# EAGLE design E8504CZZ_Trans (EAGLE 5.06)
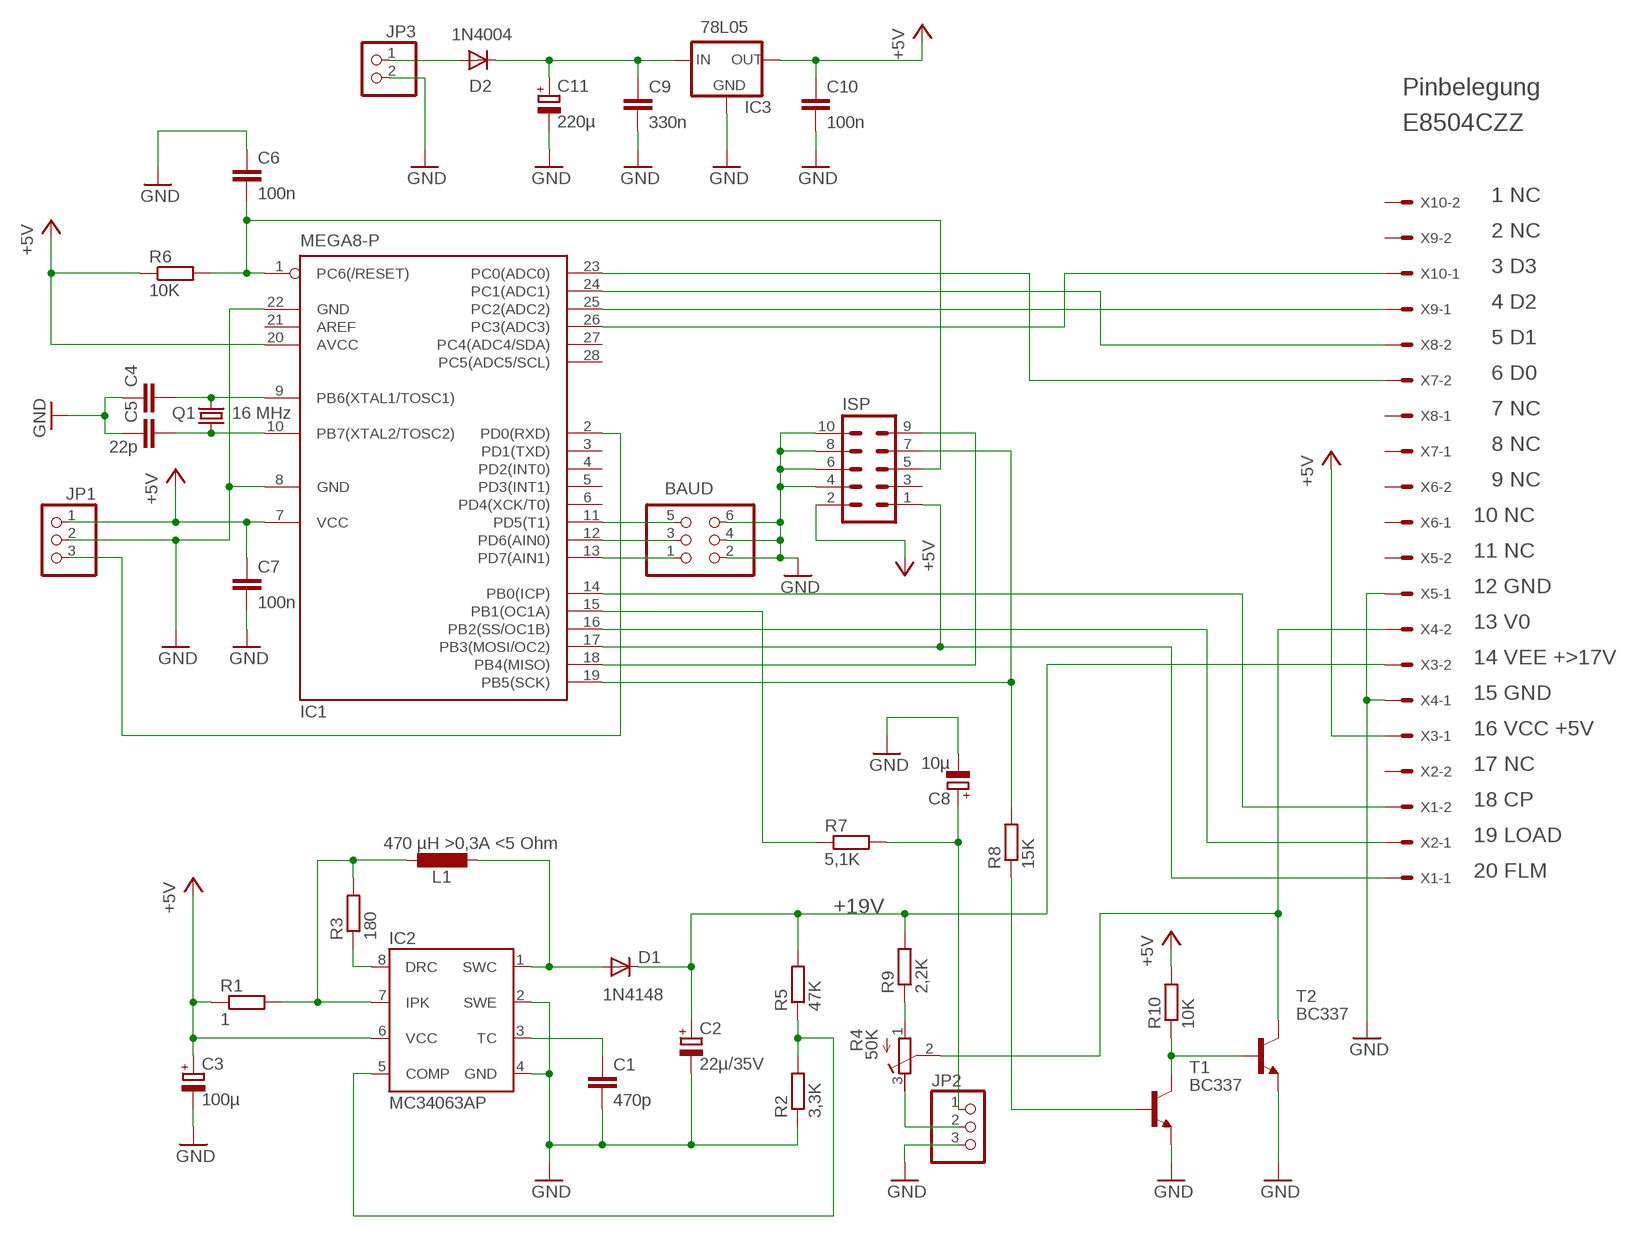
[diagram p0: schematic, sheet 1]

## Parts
BAUD  PINHD-2X3  [2X03]
C1  470p  C-EU025-024X044  [C025-024X044]
C2  22µ/35V  CPOL-EUE2-5  [E2-5]
C3  100µ  CPOL-EUE2.5-6  [E2,5-6]
C4  C-EU025-024X044  [C025-024X044]
C5  22p  C-EU025-024X044  [C025-024X044]
C6  100n  C-EU025-024X044  [C025-024X044]
C7  100n  C-EU025-024X044  [C025-024X044]
C8  10µ  CPOL-EUE2-5  [E2-5]
C9  330n  C-EU025-024X044  [C025-024X044]
C10  100n  C-EU025-024X044  [C025-024X044]
C11  220µ  CPOL-EUE3.5-8  [E3,5-8]
D1  1N4148  1N4148DO35-7  [DO35-7]
D2  1N4004  [DO41-10]
IC1  MEGA8-P  [DIL28-3]
IC2  MC34063AP  [DIL-08]
IC3  78L05  78LXX  [78LXX]
ISP  ML10  [ML10]
JP1  PINHD-1X3  [1X03]
JP2  PINHD-1X3  [1X03]
JP3  PINHD-1X2  [1X02]
L1  470 µH >0,3A <5 Ohm  L-EU0204/5  [0204/5]
Q1  16 MHz  CRYSTALHC49S  [HC49/S]
R1  1  R-EU_0207/10  [0207/10]
R2  3,3K  R-EU_0207/10  [0207/10]
R3  180  R-EU_0207/10  [0207/10]
R4  50K  R-TRIMM64W  [RTRIM64W]
R5  47K  R-EU_0207/10  [0207/10]
R6  10K  R-EU_0207/10  [0207/10]
R7  5,1K  R-EU_0207/10  [0207/10]
R8  15K  R-EU_0207/15  [0207/15]
R9  2,2K  R-EU_0207/10  [0207/10]
R10  10K  R-EU_0207/10  [0207/10]
T1  BC337  [TO92]
T2  BC337  [TO92]
X1  87758-0216  [87758-0216]
X2  87758-0216  [87758-0216]
X3  87758-0216  [87758-0216]
X4  87758-0216  [87758-0216]
X5  87758-0216  [87758-0216]
X6  87758-0216  [87758-0216]
X7  87758-0216  [87758-0216]
X8  87758-0216  [87758-0216]
X9  87758-0216  [87758-0216]
X10  87758-0216  [87758-0216]

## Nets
+5V: C3.+ C7.1 C10.1 IC1.7(VCC) IC1.20(AVCC) IC2.6(VCC) IC3.OUT ISP.2 JP1.1 R1.1 R6.1 R10.2 X3.1
+19V: C2.+ D1.C R5.2 R9.2 X3.2
CP: IC1.14(PB0(ICP)) X1.2
D0: IC1.23(PC0(ADC0)) X7.2
D1: IC1.24(PC1(ADC1)) X8.2
D2: IC1.25(PC2(ADC2)) X9.1
D3: IC1.26(PC3(ADC3)) X10.1
FLM: IC1.17(PB3(MOSI/OC2)) ISP.1 X1.1
GND: BAUD.2 BAUD.4 BAUD.6 C1.2 C2.- C3.- C4.1 C5.1 C6.1 C7.2 C8.- C9.2 C10.2 C11.- IC1.8(GND) IC1.22(GND) IC2.2(SWE) IC2.4(GND) IC3.GND ISP.4 ISP.6 ISP.8 ISP.10 JP1.2 JP2.3 JP3.2 R2.1 T1.1(E) T2.1(E) X4.1 X5.1
LOAD: IC1.16(PB2(SS/OC1B)) X2.1
MISO: IC1.18(PB4(MISO)) ISP.9
N$1: IC1.2(PD0(RXD)) JP1.3
N$2: JP2.2 R4.3(A)
N$6: IC1.15(PB1(OC1A)) R7.1
N$8: C8.+ JP2.1 R7.2
N$9: D2.A JP3.1
N$10: IC2.5(COMP) R2.2 R5.1
N$11: C5.2 IC1.10(PB7(XTAL2/TOSC2)) Q1.1
N$12: C4.2 IC1.9(PB6(XTAL1/TOSC1)) Q1.2
N$13: IC2.7(IPK) L1.1 R1.2 R3.2
N$14: BAUD.1 IC1.13(PD7(AIN1))
N$15: IC2.8(DRC) R3.1
N$16: C9.1 C11.+ D2.C IC3.IN
N$17: D1.A IC2.1(SWC) L1.2
N$19: BAUD.3 IC1.12(PD6(AIN0))
N$20: BAUD.5 IC1.11(PD5(T1))
N$21: C1.1 IC2.3(TC)
N$23: R10.1 T1.3(C) T2.2(B)
N$24: R8.1 T1.2(B)
N$25: R4.1(E) R9.1
RESET: C6.2 IC1.1(PC6(/RESET)) ISP.5 R6.2
SCK: IC1.19(PB5(SCK)) ISP.7 R8.2
VSS: R4.2(S) T2.3(C) X4.2
Unconnected: IC1.3(PD1(TXD)) IC1.4(PD2(INT0)) IC1.5(PD3(INT1)) IC1.6(PD4(XCK/T0)) IC1.21(AREF) IC1.27(PC4(ADC4/SDA)) IC1.28(PC5(ADC5/SCL)) ISP.3 X2.2 X5.2 X6.1 X6.2 X7.1 X8.1 X9.2 X10.2

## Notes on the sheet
- Pinbelegung
- E8504CZZ
- 1 NC
- 2 NC
- 3 D3
- 4 D2
- 5 D1
- 6 D0
- 7 NC
- 8 NC
- 9 NC
- 10 NC
- 11 NC
- 12 GND
- 13 V0
- 14 VEE +>17V
- 15 GND
- 16 VCC +5V
- 17 NC
- 18 CP
- 19 LOAD
- 20 FLM

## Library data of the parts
BAUD = pinhead:PINHD-2X3: PIN HEADER
C1 C4-C7 C9 C10 = rcl:C-EU: CAPACITOR, European symbol
C2 C3 C8 C11 = rcl:CPOL-EU: POLARIZED CAPACITOR, European symbol
D1 = diode:1N4148: DIODE
D2 = diode:1N4004: DIODE
IC1 = atmel:MEGA8-P: MICROCONTROLLER 8 Kbytes FLASH, 1 kbytes SRAM, 512 bytes EEPROM, USART, 4-channel 10 bit ADC, 2-channel 8 bit ADC Pin compatible with Atmega48, ATMega88, ATMega168 Source: avr.lbr
IC2 = v-reg-3:MC34063A: 1.5A Step-Up/Down/Inverting Switching Regulator NPN Darlington Switch, Vin 3V to 40V, Current Limiter Input, adjustable Frequency up to 100kHz
IC3 = v-reg:78LXX: VOLTAGE REGULATOR
ISP = con-harting-ml:ML10: HARTING
JP1 JP2 = pinhead:PINHD-1X3: PIN HEADER
JP3 = pinhead:PINHD-1X2: PIN HEADER
L1 = rcl:L-EU: INDUCTOR, European symbol
Q1 = crystal:CRYSTAL: CRYSTAL
R1-R3 R5-R10 = rcl:R-EU_: RESISTOR, European symbol
R4 = rcl:R-TRIMM: Trimm resistor
T1 = transistor-npn:BC337*: NPN Transistor
T2 = transistor:BC337: NPN TRANSISTOR
X1-X10 = con-molex:87758-0216: 2 Pin - 2mm Dual Row Single Wafer, Vertical T/H HDR

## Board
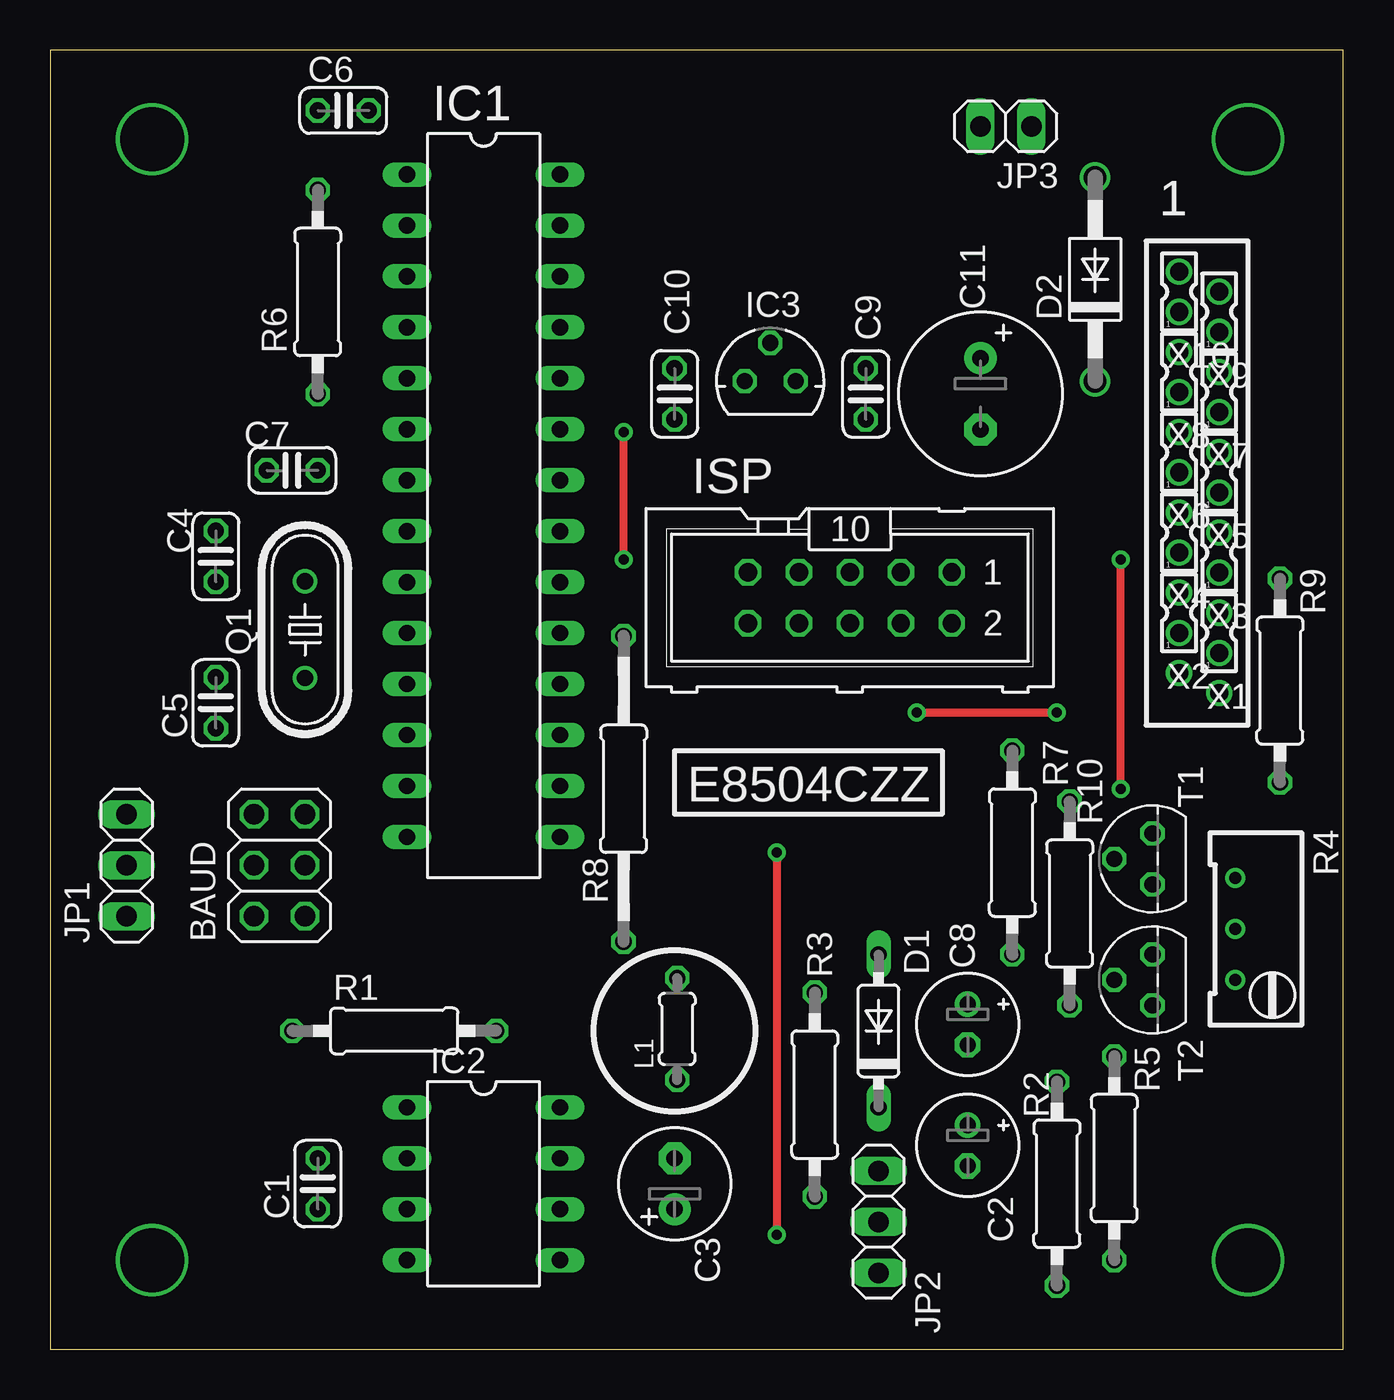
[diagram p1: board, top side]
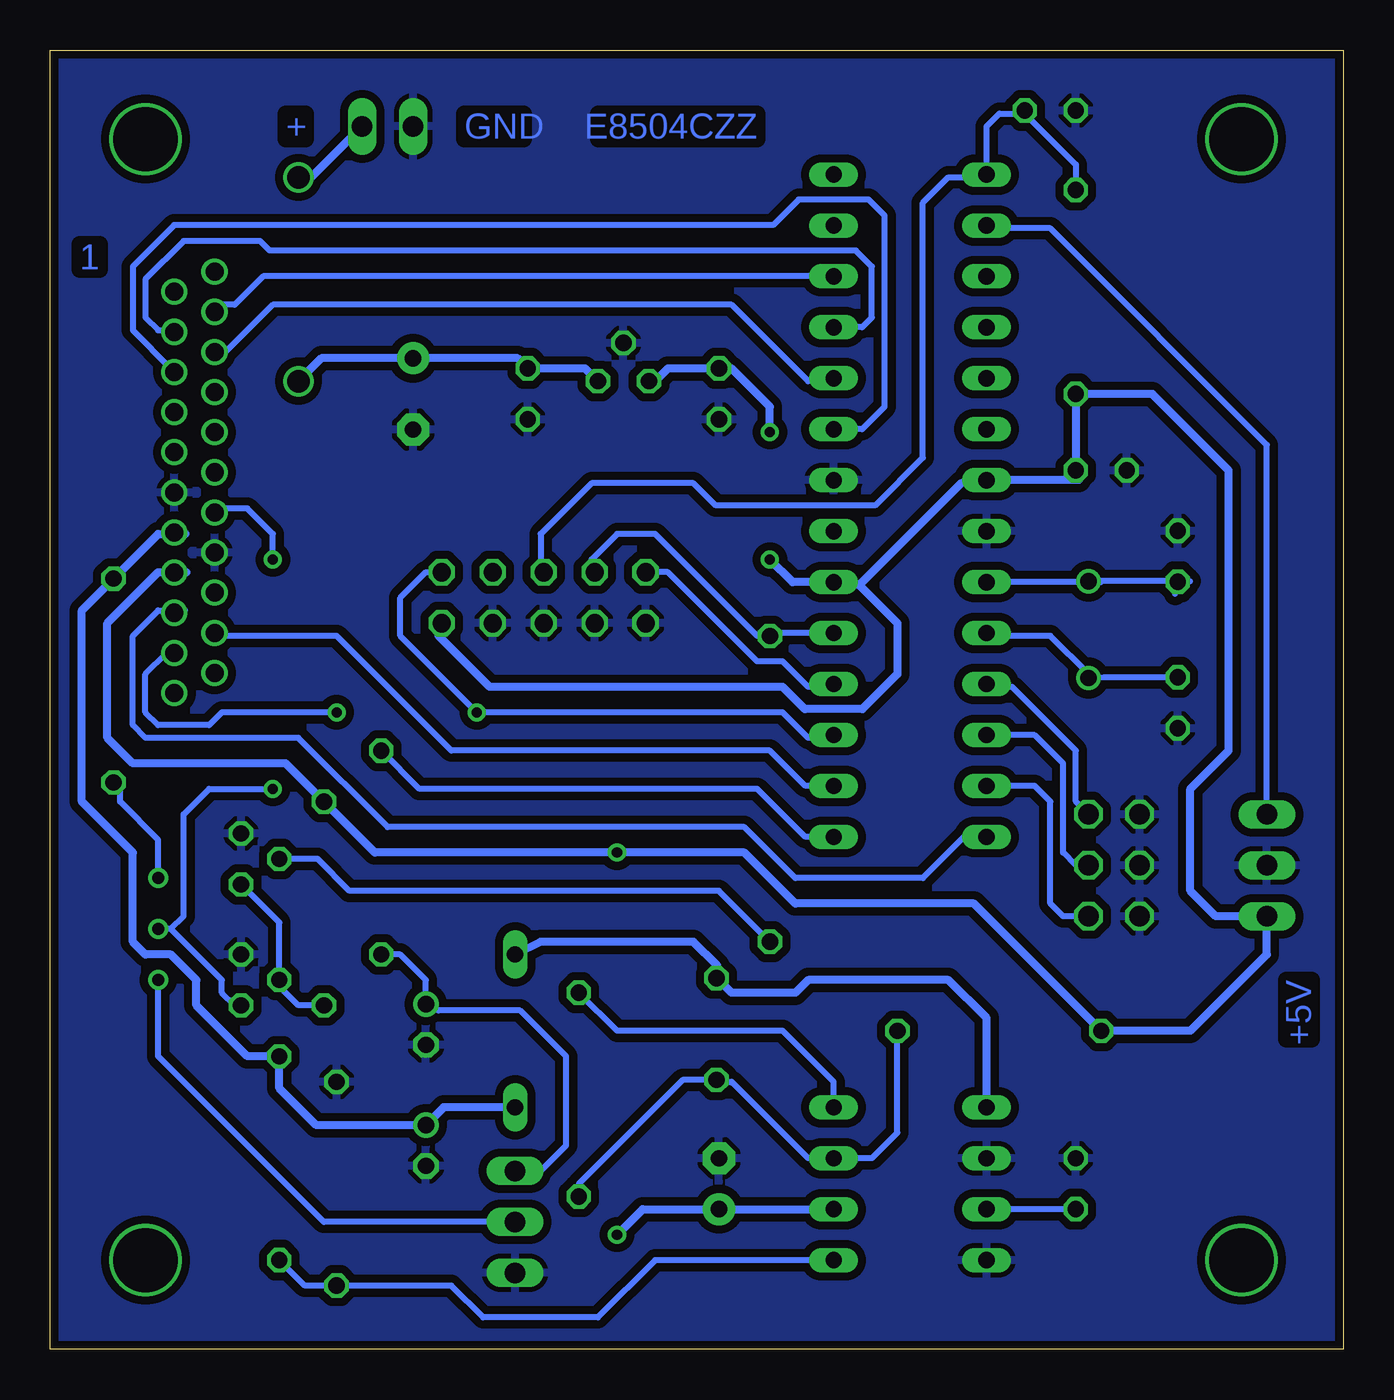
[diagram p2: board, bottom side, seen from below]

Size 64.44 x 64.76 mm. Coordinates in mm from the lower left corner, seen from the top.
Outline: 0,0 64.44,0 64.44,64.76 0,64.76 0,0
Copper layers (1*16): Top 0.035mm / dielectric 1.5mm / Bottom 0.035mm
Design rules "ZWILLING": minimum track width 0.2mm, minimum drill 0.5mm, track to track 0.2mm, track to pad 0.2mm, pad to pad 0.15mm, via to via 0.2mm, smd to smd 0mil, copper to edge 0.2mm, drill to drill 0.2mm, minimum pad ring 0.2mm, minimum via ring 0.2mm, stop-mask expansion 0.1mm, vias tented up to drill 0mil, thermal gap 10mil

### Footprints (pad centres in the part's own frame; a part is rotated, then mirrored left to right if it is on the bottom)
2X03 = drill 1.016 octagon: 1 -2.54,-1.27; 2 -2.54,1.27; 3 0,-1.27; 4 0,1.27; 5 2.54,-1.27; 6 2.54,1.27
C025-024X044 = drill 0.813 octagon: 1 -1.27,0; 2 1.27,0
E2-5 = drill 0.813 pad 1.27 round: + -1.016,0 | drill 0.813 pad 1.27 octagon: - 1.016,0
E2,5-6 = drill 0.813 pad 1.6 round: + -1.27,0 | drill 0.813 pad 1.6 octagon: - 1.27,0
E3,5-8 = drill 0.813 pad 1.6 round: + -1.778,0 | drill 0.813 pad 1.6 octagon: - 1.778,0
DO35-7 = drill 0.813 long: A 3.81,0; C -3.81,0
DO41-10 = drill 1.118 round: A 5.08,0; C -5.08,0
DIL28-3 = drill 0.813 long: 1 -16.51,-3.81; 2 -13.97,-3.81; 3 -11.43,-3.81; 4 -8.89,-3.81; 5 -6.35,-3.81; 6 -3.81,-3.81; 7 -1.27,-3.81; 8 1.27,-3.81; 9 3.81,-3.81; 10 6.35,-3.81; 11 8.89,-3.81; 12 11.43,-3.81; 13 13.97,-3.81; 14 16.51,-3.81; 15 16.51,3.81; 16 13.97,3.81; 17 11.43,3.81; 18 8.89,3.81; 19 6.35,3.81; 20 3.81,3.81; 21 1.27,3.81; 22 -1.27,3.81; 23 -3.81,3.81; 24 -6.35,3.81; 25 -8.89,3.81; 26 -11.43,3.81; 27 -13.97,3.81; 28 -16.51,3.81
DIL-08 = drill 0.813 long: 1 -3.81,-3.81; 2 -1.27,-3.81; 3 1.27,-3.81; 4 3.81,-3.81; 5 3.81,3.81; 6 1.27,3.81; 7 -1.27,3.81; 8 -3.81,3.81
78LXX = drill 0.813 octagon: GND 0,1.905; IN 1.27,0; OUT -1.27,0
ML10 = drill 0.914 octagon: 1 -5.08,-1.27; 2 -5.08,1.27; 3 -2.54,-1.27; 4 -2.54,1.27; 5 0,-1.27; 6 0,1.27; 7 2.54,-1.27; 8 2.54,1.27; 9 5.08,-1.27; 10 5.08,1.27
1X03 = drill 1.016 long: 1 -2.54,0; 2 0,0; 3 2.54,0
1X02 = drill 1.016 long: 1 -1.27,0; 2 1.27,0
0204/5 = drill 0.813 octagon: 1 -2.54,0; 2 2.54,0
HC49/S = drill 0.813 round: 1 -2.413,0; 2 2.413,0
0207/10 = drill 0.813 octagon: 1 -5.08,0; 2 5.08,0
RTRIM64W = drill 0.61 round: 1 1.27,-2.54; 2 1.27,0; 3 1.27,2.54
0207/15 = drill 0.813 octagon: 1 -7.62,0; 2 7.62,0
TO92 = drill 0.813 octagon: 1 1.27,0; 2 0,1.905; 3 -1.27,0
87758-0216 = drill 0.9 pad 1.27 round: 1 0,-1; 2 0,1

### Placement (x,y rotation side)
BAUD  11.43,24.13 90 top
C1  13.34,8.26 90 top
C2  45.72,10.16 270 top
C3  31.11,8.26 90 top
C4  8.26,39.53 270 top
C5  8.26,32.23 90 top
C6  14.61,61.75 0 top
C7  12.06,43.81 180 top
C8  45.72,16.19 270 top
C9  40.64,47.62 270 top
C10  31.11,47.62 270 top
C11  46.35,47.62 270 top
D1  41.27,15.88 90 top
D2  52.07,53.34 90 top
IC1  21.59,42.05 270 top
IC2  21.59,8.26 270 top
IC3  35.88,48.26 0 top
ISP  39.85,37.47 180 top
JP1  3.81,24.13 90 top
JP2  41.27,6.35 270 top
JP3  47.62,60.96 180 top
L1  31.24,15.97 90 top
Q1  12.7,35.88 90 top
R1  17.14,15.88 0 top
R2  50.16,8.26 270 top
R3  38.1,12.7 270 top
R4  60.33,20.95 180 top
R5  53.02,9.53 90 top
R6  13.34,52.7 90 top
R7  47.94,24.77 270 top
R8  28.57,27.94 90 top
R9  61.28,33.34 90 top
R10  50.8,22.23 90 top
T1  54.93,24.45 90 top
T2  54.93,18.41 90 top
X1  58.25,35.72 0 top
X2  56.25,36.72 0 top
X3  58.25,39.72 0 top
X4  56.25,40.72 0 top
X5  58.25,43.72 0 top
X6  56.25,44.72 0 top
X7  58.25,47.72 0 top
X8  56.25,48.72 0 top
X9  58.25,51.72 0 top
X10  56.25,52.72 0 top

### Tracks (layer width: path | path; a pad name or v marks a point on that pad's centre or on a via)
+5V  (via drill 0.5)
  Top 0.406: v36.2,24.77 v36.2,5.71 | v28.57,39.37 v28.57,45.72
  Bottom 0.406: IC2.6 C3.+ 34.92,6.99 v36.2,5.71 | X3.1 57.63,38.73 59.05,38.73 61.59,36.2 61.59,30.48 60.33,29.21 52.7,29.21 R10.2 48.26,24.77 v36.2,24.77 29.84,24.77 27.3,22.23 18.41,22.23 R1.1 7.62,15.88 3.81,19.68 JP1.1 6.35,21.59 7.62,22.86 7.62,27.94 5.71,29.84 5.71,43.81 9.53,47.62 R6.1 C7.1 13.18,43.34 17,43.34 IC1.7 17.92,43.18 19.05,43.18 24.13,38.1 | 24.13,38.1 22.23,36.2 22.23,33.66 23.97,31.91 26.83,31.91 27.94,33.02 42.55,33.02 45.09,35.56 45.09,36.04 ISP.2 | 24.13,38.1 25.26,38.1 IC1.20 27.45,38.24 v28.57,39.37 | IC3.OUT 34.29,48.26 33.66,48.9 C10.1 30.48,48.9 28.57,46.99 v28.57,45.72
+19V
  Bottom 0.406: X3.2 57.69,40.64 59.05,40.64 62.87,36.83 | D1.C 44.83,12.06 C2.+ 51.18,11.18 53.02,13.02 R5.2 54.61,14.61 57.15,17.14 57.15,18.41 58.42,19.68 59.69,19.68 60.33,20.32 60.33,24.77 62.87,27.3 62.87,36.83 | 62.87,36.83 R9.2
CP
  Bottom 0.305: IC1.14 18.91,25.54 20.95,23.5 27.3,23.5 29.84,26.04 47.62,26.04 52.07,30.48 59.69,30.48 60.33,31.11 60.33,35.56 59.05,36.83 57.73,36.83 X1.2
D0
  Bottom 0.305: IC1.23 23.99,45.86 22.86,46.99 22.86,56.52 23.65,57.31 27.15,57.31 28.42,56.04 58.26,56.04 60.33,53.98 60.33,50.8 58.42,48.9 57.8,48.9 X7.2
D1
  Bottom 0.305: IC1.24 25.54,48.26 26.67,48.26 30.48,52.07 53.34,52.07 55.88,49.53 56.06,49.53 X8.2
D2
  Bottom 0.305: IC1.25 23.99,50.94 23.5,51.44 23.5,53.98 24.29,54.77 53.5,54.77 53.98,55.24 57.78,55.24 59.69,53.34 59.69,51.44 59.05,50.8 58.34,50.8 X9.1
D3
  Bottom 0.305: IC1.26 53.83,53.48 55.24,52.07 55.9,52.07 X10.1
FLM  (via drill 0.5)
  Top 0.406: v43.18,31.75 v50.16,31.75
  Bottom 0.305: X1.1 58.63,34.72 59.69,33.66 59.69,31.75 59.05,31.11 56.52,31.11 55.88,31.75 v50.16,31.75 | ISP.1 45.72,38.73 46.99,37.47 46.99,35.56 v43.18,31.75 27.94,31.75 26.67,30.48 25.54,30.48 IC1.17
GND
  pour Bottom (isolate 0.406): -1.91,66.67 67.31,66.67 67.31,-2.54 -1.91,-2.54
LOAD
  Bottom 0.305: IC1.16 26.81,28.08 28.57,29.84 44.45,29.84 50.16,35.56 56.09,35.56 | 56.09,35.56 55.88,35.56 | 56.09,35.56 X2.1
MISO
  Bottom 0.305: IC1.18 25.54,33.02 26.67,33.02 27.94,34.29 29.21,34.29 33.66,38.73 ISP.9
N$1
  Bottom 0.305: IC1.2 17.64,55.88 14.61,55.88 3.81,45.09 JP1.3
N$2
  Bottom 0.305: JP2.2 50.8,6.35 59.05,14.61 R4.3
N$3  (via drill 3.2)
  other vias: 5.08,60.33
N$4  (via drill 3.2)
  other vias: 59.69,60.33
N$5  (via drill 3.2)
  other vias: 59.69,4.45
N$6
  Bottom 0.305: IC1.15 26.81,25.54 29.21,27.94 46.04,27.94 R7.1
N$7  (via drill 3.2)
  other vias: 5.08,4.45
N$8
  Bottom 0.305: JP2.1 40.01,8.89 38.73,10.16 38.73,14.61 41.02,16.89 45.09,16.89 C8.+ 45.72,18.41 46.99,19.68 R7.2
N$9
  Bottom 0.406: D2.A 51.44,58.42 JP3.1
N$10
  Bottom 0.305: IC2.5 34.29,4.45 37.15,1.59 42.86,1.59 44.45,3.17 R2.2 51.75,3.17 R5.1
N$11
  Bottom 0.305: C5.2 11.94,33.5 Q1.1 12.7,33.66 14.61,35.56 17.64,35.56 IC1.10
N$12
  Bottom 0.305: IC1.9 12.11,38.24 Q1.2 7.65,38.29 C4.2 8.38,37.66
N$13
  Bottom 0.305: R3.2 38.1,8.26 32.92,13.43 L1.1 31.11,13.3 30.48,13.3 30.48,13.34 26.67,9.53 IC2.7 23.5,9.53 22.23,10.79 R1.2
N$14
  Bottom 0.305: BAUD.1 13.97,21.59 14.61,22.23 14.61,27.3 15.38,28.08 IC1.13
N$15
  Bottom 0.305: IC2.8 25.4,13.34 27.94,15.88 36.2,15.88 R3.1
N$16
  Bottom 0.406: IC3.IN 37.78,48.9 C9.1 41.15,49.4 C11.+ 50.93,49.4 D2.C
N$17
  Bottom 0.406: IC2.1 17.78,16.51 19.68,18.41 26.67,18.41 27.3,17.78 30.48,17.78 31.11,18.41 31.15,18.41 L1.2 31.21,19.14 32.38,20.32 40.01,20.32 D1.A
N$18  (via drill 0.9)
  other vias: 58.25,32.72
N$19
  Bottom 0.305: BAUD.3 13.34,24.13 13.97,24.77 13.97,29.21 15.38,30.62 IC1.12
N$20
  Bottom 0.305: IC1.11 17.64,33.02 16.51,33.02 13.34,29.84 13.34,27.3 BAUD.5
N$21
  Bottom 0.305: C1.1 IC2.3
N$22  (via drill 0.9)
  other vias: 56.25,33.72
N$23
  Bottom 0.305: R10.1 52.07,17.14 53.02,18.1 T2.2 53.02,21.27 T1.3
N$24
  Bottom 0.305: R8.1 31.11,22.86 49.53,22.86 51.12,24.45 T1.2
N$25
  Bottom 0.305: R4.1 59.05,25.4 60.96,27.3 60.96,27.94 R9.1
RESET
  Bottom 0.305: 17.14,58.42 19.68,58.42 20.95,57.15 20.95,44.45 23.34,42.07 27.78,42.07 31.27,42.07 32.38,43.18 37.47,43.18 40.01,40.64 40.01,38.89 ISP.5 | IC1.1 17.78,60.96 17.14,61.59 15.88,61.59 | 15.88,61.59 13.34,59.05 R6.2 | 15.88,61.59 C6.2
  Bottom 0.406: 17.14,58.42 17.64,58.42 IC1.1
SCK
  Bottom 0.305: IC1.19 28.43,35.7 R8.2 29.21,35.56 34.29,40.64 36.2,40.64 37.47,39.37 37.47,38.89 ISP.7
VSS  (via drill 0.5)
  Top 0.406: v53.34,27.94 v53.34,39.37
  Bottom 0.305: 56.13,41.59 X4.2 56.05,41.91 54.61,41.91 53.34,40.64 v53.34,39.37 | v53.34,27.94 56.52,27.94 57.78,26.67 57.78,21.59 58.42,20.95 | 58.42,20.95 R4.2 | 58.42,20.95 55.88,18.41 55.88,17.78 55.24,17.14 T2.3

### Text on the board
Bottom: E8504CZZ | GND | + | 1 | +5V
tNames: 1 | E8504CZZ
